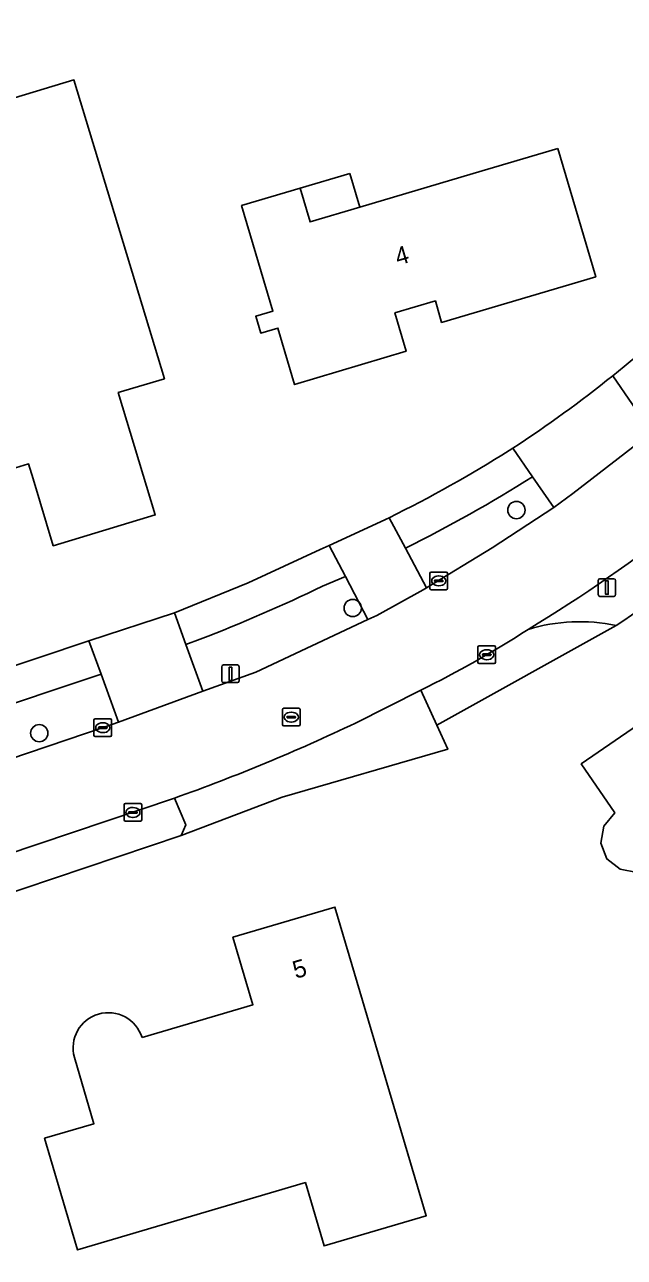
# Model space of a CAD drawing. Extents: x 162417 to 163722, y 384268 to 385417.
# Drawn here: x 163386 to 163420, y 384586 to 384656 of the extents above; entities that cross this region are included whole.
import ezdxf

# ---------------------------------------------------------------- set-up
doc = ezdxf.new("R2010")
doc.units = 0
for name, color, linetype in [('IMGEO_Berm_groen', 7, 'Continuous'), ('IMGEO_Boom', 7, 'Continuous'), ('IMGEO_Erf', 7, 'Continuous'), ('IMGEO_Groenvoorziening', 7, 'Continuous'), ('IMGEO_Kolk', 7, 'Continuous'), ('IMGEO_Lichtmast', 7, 'Continuous'), ('IMGEO_Pand', 7, 'Continuous'), ('IMGEO_Pand_nummerreeks', 7, 'Continuous'), ('IMGEO_Pand_overbouw', 7, 'Continuous'), ('IMGEO_Rijbaan_lokaal_open', 7, 'Continuous'), ('IMGEO_Rioolput', 7, 'Continuous'), ('IMGEO_Voetpad_open', 7, 'Continuous')]:
    doc.layers.add(name, color=color, linetype=linetype)

msp = doc.modelspace()

# ---------------------------------------------------------------- linework, layer by layer
at = {"layer": 'IMGEO_Berm_groen'}
for points in [[(163416.038, 384628.57), (163414.832, 384630.315)], [(163407.636, 384626.267), (163408.832, 384624.02), (163412.543, 384626.296), (163416.038, 384628.57)], [(163405.506, 384622.218), (163404.226, 384624.67), (163402.927, 384624.111)], [(163395.999, 384621.107), (163395.186, 384620.803), (163396.153, 384618.151), (163399.158, 384619.244), (163405.506, 384622.218)]]:
    msp.add_lwpolyline(points, dxfattribs=at)
msp.add_lwpolyline([(163390.546, 384616.112), (163391.36, 384616.408), (163390.37, 384619.126), (163375.772, 384614.24), (163376.658, 384611.416)], close=True, dxfattribs=at)
for centre, radius, start, end in [((163371.727, 384698.521), 80.685, 296.42647, 302.29206), ((163364.309, 384703.683), 88.448, 290.99513, 295.88824)]:
    msp.add_arc(centre, radius, start, end, dxfattribs=at)
at = {"layer": 'IMGEO_Boom'}
for centre in [(163413.924, 384628.428), (163404.643, 384622.873), (163386.868, 384615.776)]:
    msp.add_circle(centre, 0.489, dxfattribs=at)
at = {"layer": 'IMGEO_Erf'}
for points in [[(163310.09, 384681.76), (163333.508, 384602.071), (163340.928, 384604.472), (163346.471, 384606.34), (163371.048, 384614.758), (163375.186, 384616.159), (163389.679, 384621.017), (163394.532, 384622.596), (163398.708, 384624.299), (163402.801, 384626.194), (163403.314, 384626.415), (163406.716, 384627.995)], [(163413.514, 384631.806), (163413.713, 384631.935)], [(163419.582, 384621.874), (163409.408, 384616.22), (163410.03, 384614.861), (163400.639, 384612.147), (163394.917, 384609.966), (163384.126, 384606.347), (163382.571, 384605.826), (163379.98, 384604.957), (163377.103, 384603.845), (163372.405, 384602.287), (163358.873, 384597.777), (163355.069, 384596.509), (163354.943, 384596.875), (163344.075, 384593.215), (163344.183, 384592.925), (163342.307, 384592.282)], [(163403.635, 384605.913), (163405.052, 384601.119), (163408.811, 384588.401), (163403.019, 384586.69), (163401.957, 384590.287), (163389.04, 384586.469), (163388.587, 384588.004), (163387.17, 384592.799), (163389.971, 384593.627), (163388.86, 384597.387)], [(163392.697, 384598.51), (163398.987, 384600.369), (163397.853, 384604.204), (163403.635, 384605.913)]]:
    msp.add_lwpolyline(points, dxfattribs=at)
for points in [[(163392.516, 384640.667), (163393.965, 384635.882), (163391.345, 384635.089), (163393.445, 384628.155), (163387.663, 384626.41), (163386.518, 384630.192), (163386.261, 384631.043), (163384.28, 384630.444), (163384.538, 384629.593), (163380.261, 384628.298), (163379.31, 384631.443), (163376.692, 384630.651), (163375.243, 384635.437), (163374.953, 384636.394), (163377.573, 384637.187), (163376.623, 384640.332), (163382.891, 384642.229), (163381.746, 384646.012), (163380.405, 384650.271), (163388.837, 384652.823)], [(163416.266, 384648.938), (163418.425, 384641.662), (163409.685, 384639.076), (163409.329, 384640.29), (163407.033, 384639.616), (163407.664, 384637.439), (163401.35, 384635.549), (163400.4, 384638.751), (163399.431, 384638.464), (163399.146, 384639.421), (163400.114, 384639.709), (163398.338, 384645.7), (163401.655, 384646.683), (163402.221, 384644.775), (163405.042, 384645.611), (163411.472, 384647.517)], [(163423.426, 384619.015), (163423.504, 384619.857), (163425.24, 384621.047), (163426.06, 384620.847), (163426.722, 384620.31), (163434.524, 384625.652), (163437.361, 384621.535), (163444.73, 384610.844), (163436.077, 384604.88), (163431.875, 384610.985), (163423.588, 384605.386), (163421.696, 384608.187), (163420.775, 384607.881), (163419.813, 384608.066), (163419.044, 384608.641), (163418.702, 384609.538), (163418.883, 384610.501), (163419.499, 384611.264), (163417.6, 384614.035), (163423.689, 384618.208)]]:
    msp.add_lwpolyline(points, close=True, dxfattribs=at)
for centre, radius, start, end in [((163373.98, 384692.802), 72.684, 308.65684, 314.01186), ((163373.676, 384693.163), 73.156, 303.18096, 308.66682), ((163368.694, 384696.602), 90.409, 304.2543, 314.94032), ((163372.795, 384696.472), 76.418, 296.35239, 302.19812), ((163390.786, 384597.921), 1.999, 17.12637, 195.50067)]:
    msp.add_arc(centre, radius, start, end, dxfattribs=at)
at = {"layer": 'IMGEO_Groenvoorziening'}
for points in [[(163408.495, 384618.212), (163409.408, 384616.22), (163419.582, 384621.874)], [(163384.126, 384606.347), (163394.917, 384609.966), (163395.176, 384610.568), (163394.546, 384612.095), (163382.96, 384608.203)]]:
    msp.add_lwpolyline(points, dxfattribs=at)
for centre, radius, start, end in [((163417.49, 384612.22), 9.878, 77.77644, 107.10513), ((163381.624, 384672.76), 60.808, 296.2254, 302.82367)]:
    msp.add_arc(centre, radius, start, end, dxfattribs=at)
at = {"layer": 'IMGEO_Kolk'}
for p, q in [((163409.019, 384623.988), (163409.019, 384624.84)), ((163409.094, 384624.914), (163409.946, 384624.914)), ((163410.02, 384624.84), (163410.02, 384623.988)), ((163409.278, 384624.408), (163409.278, 384624.42)), ((163409.716, 384624.371), (163409.318, 384624.371)), ((163409.321, 384624.457), (163409.719, 384624.457)), ((163409.53, 384624.134), (163409.505, 384624.134)), ((163409.507, 384624.694), (163409.532, 384624.694)), ((163409.762, 384624.42), (163409.762, 384624.408)), ((163409.946, 384623.914), (163409.094, 384623.914)), ((163411.74, 384619.798), (163411.74, 384620.65)), ((163411.815, 384620.724), (163412.667, 384620.724)), ((163412.741, 384620.65), (163412.741, 384619.798)), ((163411.999, 384620.218), (163411.999, 384620.23)), ((163412.437, 384620.181), (163412.039, 384620.181)), ((163412.042, 384620.267), (163412.44, 384620.267)), ((163412.251, 384619.944), (163412.226, 384619.944)), ((163412.228, 384620.504), (163412.253, 384620.504)), ((163412.483, 384620.23), (163412.483, 384620.218)), ((163412.667, 384619.724), (163411.815, 384619.724)), ((163389.968, 384615.659), (163389.968, 384616.511)), ((163390.043, 384616.585), (163390.895, 384616.585)), ((163390.456, 384616.365), (163390.481, 384616.365)), ((163390.969, 384616.511), (163390.969, 384615.659)), ((163390.227, 384616.079), (163390.227, 384616.091)), ((163390.665, 384616.042), (163390.267, 384616.042)), ((163390.27, 384616.128), (163390.668, 384616.128)), ((163390.479, 384615.805), (163390.454, 384615.805)), ((163390.711, 384616.091), (163390.711, 384616.079)), ((163390.895, 384615.585), (163390.043, 384615.585)), ((163391.677, 384610.854), (163391.677, 384611.706)), ((163391.752, 384611.78), (163392.604, 384611.78)), ((163392.165, 384611.56), (163392.19, 384611.56)), ((163392.678, 384611.706), (163392.678, 384610.854)), ((163392.604, 384610.78), (163391.752, 384610.78)), ((163391.936, 384611.274), (163391.936, 384611.286)), ((163392.374, 384611.237), (163391.976, 384611.237)), ((163391.979, 384611.323), (163392.377, 384611.323)), ((163392.188, 384611), (163392.163, 384611)), ((163392.42, 384611.286), (163392.42, 384611.274))]:
    msp.add_line(p, q, dxfattribs=at)
for points in [[(163409.019, 384623.988), (163409.019, 384624.84)], [(163409.094, 384624.914), (163409.946, 384624.914)], [(163410.02, 384624.84), (163410.02, 384623.988)], [(163409.946, 384623.914), (163409.094, 384623.914)], [(163411.74, 384619.798), (163411.74, 384620.65)], [(163411.815, 384620.724), (163412.667, 384620.724)], [(163412.741, 384620.65), (163412.741, 384619.798)], [(163412.667, 384619.724), (163411.815, 384619.724)], [(163389.968, 384615.659), (163389.968, 384616.511)], [(163390.043, 384616.585), (163390.895, 384616.585)], [(163390.969, 384616.511), (163390.969, 384615.659)], [(163390.895, 384615.585), (163390.043, 384615.585)], [(163391.677, 384610.854), (163391.677, 384611.706)], [(163391.752, 384611.78), (163392.604, 384611.78)], [(163392.678, 384611.706), (163392.678, 384610.854)], [(163392.604, 384610.78), (163391.752, 384610.78)]]:
    msp.add_lwpolyline(points, dxfattribs=at)
for centre, radius, start, end in [((163409.096, 384624.838), 0.0765, 91.55205, 178.44795), ((163409.096, 384624.838), 0.0765, 91.55205, 178.44795), ((163409.944, 384624.838), 0.0765, 1.55205, 88.44795), ((163409.944, 384624.838), 0.0765, 1.55205, 88.44795), ((163409.318, 384624.417), 0.0403, 85.87752, 175.75265), ((163409.315, 384624.407), 0.0366, 178.93798, 274.71019), ((163409.719, 384624.414), 0.043, 264.86636, 352.45326), ((163409.723, 384624.419), 0.0386, 1.73085, 96.63898), ((163409.096, 384623.99), 0.0765, 181.55205, 268.44795), ((163409.096, 384623.99), 0.0765, 181.55205, 268.44795), ((163409.944, 384623.99), 0.0765, 271.55205, 358.44795), ((163409.944, 384623.99), 0.0765, 271.55205, 358.44795), ((163411.817, 384620.648), 0.0765, 91.55205, 178.44795), ((163411.817, 384620.648), 0.0765, 91.55205, 178.44795), ((163412.665, 384620.648), 0.0765, 1.55205, 88.44795), ((163412.665, 384620.648), 0.0765, 1.55205, 88.44795), ((163412.039, 384620.227), 0.0403, 85.87752, 175.75265), ((163412.036, 384620.217), 0.0366, 178.93798, 274.71019), ((163412.44, 384620.224), 0.043, 264.86636, 352.45326), ((163412.444, 384620.229), 0.0386, 1.73085, 96.63898), ((163411.817, 384619.8), 0.0765, 181.55205, 268.44795), ((163411.817, 384619.8), 0.0765, 181.55205, 268.44795), ((163412.665, 384619.8), 0.0765, 271.55205, 358.44795), ((163412.665, 384619.8), 0.0765, 271.55205, 358.44795), ((163390.045, 384616.509), 0.0765, 91.55205, 178.44795), ((163390.045, 384616.509), 0.0765, 91.55205, 178.44795), ((163390.893, 384616.509), 0.0765, 1.55205, 88.44795), ((163390.893, 384616.509), 0.0765, 1.55205, 88.44795), ((163390.045, 384615.661), 0.0765, 181.55205, 268.44795), ((163390.045, 384615.661), 0.0765, 181.55205, 268.44795), ((163390.267, 384616.088), 0.0403, 85.87752, 175.75265), ((163390.264, 384616.078), 0.0366, 178.93798, 274.71019), ((163390.668, 384616.085), 0.043, 264.86636, 352.45326), ((163390.672, 384616.09), 0.0386, 1.73085, 96.63898), ((163390.893, 384615.661), 0.0765, 271.55205, 358.44795), ((163390.893, 384615.661), 0.0765, 271.55205, 358.44795), ((163391.754, 384611.704), 0.0765, 91.55205, 178.44795), ((163391.754, 384611.704), 0.0765, 91.55205, 178.44795), ((163392.602, 384611.704), 0.0765, 1.55205, 88.44795), ((163392.602, 384611.704), 0.0765, 1.55205, 88.44795), ((163391.754, 384610.856), 0.0765, 181.55205, 268.44795), ((163391.754, 384610.856), 0.0765, 181.55205, 268.44795), ((163391.976, 384611.283), 0.0403, 85.87752, 175.75265), ((163391.973, 384611.273), 0.0366, 178.93798, 274.71019), ((163392.377, 384611.28), 0.043, 264.86636, 352.45326), ((163392.381, 384611.285), 0.0386, 1.73085, 96.63898), ((163392.602, 384610.856), 0.0765, 271.55205, 358.44795), ((163392.602, 384610.856), 0.0765, 271.55205, 358.44795)]:
    msp.add_arc(centre, radius, start, end, dxfattribs=at)
for centre, major_axis, ratio, start_param, end_param in [((163409.506, 384624.414), (-0.387, 0.002), 0.722429, 4.712389, 7.853982), ((163409.531, 384624.414), (-0.39, 0.002), 0.717154, 1.570796, 4.712389), ((163412.227, 384620.224), (-0.387, 0.002), 0.722429, 4.712389, 7.853982), ((163412.252, 384620.224), (-0.39, 0.002), 0.717154, 1.570796, 4.712389), ((163390.455, 384616.085), (-0.387, 0.002), 0.722429, 4.712389, 7.853982), ((163390.48, 384616.085), (-0.39, 0.002), 0.717154, 1.570796, 4.712389), ((163392.164, 384611.28), (-0.387, 0.002), 0.722429, 4.712389, 7.853982), ((163392.189, 384611.28), (-0.39, 0.002), 0.717154, 1.570796, 4.712389)]:
    msp.add_ellipse(centre, major_axis=major_axis, ratio=ratio, start_param=start_param, end_param=end_param, dxfattribs=at)
at = {"layer": 'IMGEO_Lichtmast'}
for p, q in [((163418.56, 384623.632), (163418.56, 384624.432)), ((163418.56, 384624.432), (163418.56, 384623.632)), ((163418.66, 384624.532), (163419.45, 384624.532)), ((163419.45, 384624.532), (163418.66, 384624.532)), ((163419.55, 384624.432), (163419.55, 384623.632)), ((163419.55, 384623.632), (163419.55, 384624.432)), ((163419.45, 384623.532), (163418.66, 384623.532)), ((163418.66, 384623.532), (163419.45, 384623.532)), ((163397.213, 384618.742), (163397.213, 384619.542)), ((163397.213, 384619.542), (163397.213, 384618.742)), ((163397.313, 384619.642), (163398.103, 384619.642)), ((163398.103, 384619.642), (163397.313, 384619.642)), ((163398.203, 384619.542), (163398.203, 384618.742)), ((163398.203, 384618.742), (163398.203, 384619.542)), ((163398.103, 384618.642), (163397.313, 384618.642)), ((163397.313, 384618.642), (163398.103, 384618.642))]:
    msp.add_line(p, q, dxfattribs=at)
for points in [[(163418.98, 384624.407), (163419.13, 384624.407), (163419.13, 384623.657), (163418.98, 384623.657), (163418.98, 384624.407)], [(163397.633, 384619.517), (163397.783, 384619.517), (163397.783, 384618.767), (163397.633, 384618.767), (163397.633, 384619.517)]]:
    msp.add_lwpolyline(points, dxfattribs=at)
for centre, start, end in [((163418.66, 384624.432), 90, 180), ((163418.66, 384624.432), 90, 180), ((163419.45, 384624.432), 0, 90), ((163419.45, 384624.432), 360, 90), ((163418.66, 384623.632), 180, 270), ((163418.66, 384623.632), 180, 270), ((163419.45, 384623.632), 270, 0), ((163419.45, 384623.632), 270, 0), ((163397.313, 384619.542), 90, 180), ((163397.313, 384619.542), 90, 180), ((163398.103, 384619.542), 0, 90), ((163398.103, 384619.542), 360, 90), ((163397.313, 384618.742), 180, 270), ((163397.313, 384618.742), 180, 270), ((163398.103, 384618.742), 270, 0), ((163398.103, 384618.742), 270, 0)]:
    msp.add_arc(centre, 0.1, start, end, dxfattribs=at)
at = {"layer": 'IMGEO_Pand'}
for points in [[(163375.243, 384635.437), (163376.692, 384630.651), (163379.31, 384631.443), (163380.261, 384628.298), (163384.538, 384629.593), (163384.28, 384630.444), (163386.261, 384631.043), (163386.518, 384630.192), (163387.663, 384626.41), (163393.445, 384628.155), (163391.345, 384635.089), (163393.965, 384635.882), (163392.516, 384640.667), (163388.837, 384652.823), (163380.405, 384650.271), (163381.746, 384646.012), (163382.891, 384642.229), (163376.623, 384640.332), (163377.573, 384637.187), (163374.953, 384636.394)], [(163416.266, 384648.938), (163411.472, 384647.517), (163405.042, 384645.611), (163402.221, 384644.775), (163401.655, 384646.683), (163398.338, 384645.7), (163400.114, 384639.709), (163399.146, 384639.421), (163399.431, 384638.464), (163400.4, 384638.751), (163401.35, 384635.549), (163407.664, 384637.439), (163407.033, 384639.616), (163409.329, 384640.29), (163409.685, 384639.076), (163418.425, 384641.662)], [(163419.499, 384611.264), (163418.883, 384610.501), (163418.702, 384609.538), (163419.044, 384608.641), (163419.813, 384608.066), (163420.775, 384607.881), (163421.696, 384608.187), (163423.588, 384605.386), (163431.875, 384610.985), (163436.077, 384604.88), (163444.73, 384610.844), (163437.361, 384621.535), (163434.524, 384625.652), (163426.722, 384620.31), (163426.06, 384620.847), (163425.24, 384621.047), (163423.504, 384619.857), (163423.426, 384619.015), (163423.689, 384618.208), (163417.6, 384614.035)]]:
    msp.add_lwpolyline(points, close=True, dxfattribs=at)
msp.add_lwpolyline([(163388.86, 384597.387), (163389.971, 384593.627), (163387.17, 384592.799), (163388.587, 384588.004), (163389.04, 384586.469), (163401.957, 384590.287), (163403.019, 384586.69), (163408.811, 384588.401), (163405.052, 384601.119), (163403.635, 384605.913), (163397.853, 384604.204), (163398.987, 384600.369), (163392.697, 384598.51)], dxfattribs=at)
msp.add_arc((163390.786, 384597.921), 1.999, 17.12637, 195.50067, dxfattribs=at)
at = {"layer": 'IMGEO_Pand_overbouw'}
msp.add_lwpolyline([(163404.476, 384647.519), (163401.655, 384646.683), (163402.221, 384644.775), (163405.042, 384645.611)], close=True, dxfattribs=at)
at = {"layer": 'IMGEO_Rijbaan_lokaal_open'}
for points in [[(163421.605, 384632.827), (163417.131, 384629.372), (163416.038, 384628.57), (163412.543, 384626.296), (163408.832, 384624.02), (163408.641, 384623.903), (163406.014, 384622.456), (163405.506, 384622.218), (163399.158, 384619.244), (163396.153, 384618.151), (163391.36, 384616.408), (163390.546, 384616.112), (163376.658, 384611.416)], [(163404.799, 384616.348), (163408.495, 384618.212)], [(163317.177, 384586.045), (163324.882, 384588.717), (163325.068, 384588.78), (163335.735, 384592.381), (163354.346, 384598.613), (163358.243, 384599.918), (163371.696, 384604.423), (163376.389, 384605.995), (163381.515, 384607.717), (163382.96, 384608.203), (163394.546, 384612.095)]]:
    msp.add_lwpolyline(points, dxfattribs=at)
for centre, radius, start, end in [((163370.506, 384694.597), 85.221, 301.14686, 315.76166), ((163381.624, 384672.76), 60.808, 296.2254, 302.82367), ((163357.584, 384715.688), 109.99, 289.63659, 295.42129)]:
    msp.add_arc(centre, radius, start, end, dxfattribs=at)
at = {"layer": 'IMGEO_Rioolput'}
for p, q in [((163400.657, 384616.26), (163400.657, 384617.112)), ((163400.732, 384617.186), (163401.584, 384617.186)), ((163401.658, 384617.112), (163401.658, 384616.26)), ((163400.916, 384616.68), (163400.916, 384616.692)), ((163401.354, 384616.643), (163400.956, 384616.643)), ((163400.959, 384616.729), (163401.357, 384616.729)), ((163401.168, 384616.406), (163401.143, 384616.406)), ((163401.145, 384616.966), (163401.17, 384616.966)), ((163401.4, 384616.692), (163401.4, 384616.68)), ((163401.584, 384616.186), (163400.732, 384616.186))]:
    msp.add_line(p, q, dxfattribs=at)
for points in [[(163400.657, 384616.26), (163400.657, 384617.112)], [(163400.732, 384617.186), (163401.584, 384617.186)], [(163401.658, 384617.112), (163401.658, 384616.26)], [(163401.584, 384616.186), (163400.732, 384616.186)]]:
    msp.add_lwpolyline(points, dxfattribs=at)
for centre, radius, start, end in [((163400.734, 384617.11), 0.0765, 91.55205, 178.44795), ((163400.734, 384617.11), 0.0765, 91.55205, 178.44795), ((163401.582, 384617.11), 0.0765, 1.55205, 88.44795), ((163401.582, 384617.11), 0.0765, 1.55205, 88.44795), ((163400.956, 384616.689), 0.0403, 85.87752, 175.75265), ((163400.953, 384616.679), 0.0366, 178.93798, 274.71019), ((163401.357, 384616.686), 0.043, 264.86636, 352.45326), ((163401.361, 384616.691), 0.0386, 1.73085, 96.63898), ((163400.734, 384616.262), 0.0765, 181.55205, 268.44795), ((163400.734, 384616.262), 0.0765, 181.55205, 268.44795), ((163401.582, 384616.262), 0.0765, 271.55205, 358.44795), ((163401.582, 384616.262), 0.0765, 271.55205, 358.44795)]:
    msp.add_arc(centre, radius, start, end, dxfattribs=at)
for centre, major_axis, ratio, start_param, end_param in [((163401.144, 384616.686), (-0.387, 0.002), 0.722429, 4.712389, 7.853982), ((163401.169, 384616.686), (-0.39, 0.002), 0.717154, 1.570796, 4.712389)]:
    msp.add_ellipse(centre, major_axis=major_axis, ratio=ratio, start_param=start_param, end_param=end_param, dxfattribs=at)
at = {"layer": 'IMGEO_Voetpad_open'}
for points in [[(163413.713, 384631.935), (163414.832, 384630.315), (163416.038, 384628.57), (163417.131, 384629.372), (163421.605, 384632.827), (163420.504, 384634.421), (163419.383, 384636.043)], [(163419.383, 384636.043), (163420.504, 384634.421)], [(163414.832, 384630.315), (163413.713, 384631.935), (163413.514, 384631.806)], [(163406.716, 384627.995), (163407.636, 384626.267)], [(163402.927, 384624.111), (163404.226, 384624.67), (163403.314, 384626.415), (163402.801, 384626.194), (163398.708, 384624.299), (163394.532, 384622.596), (163395.186, 384620.803), (163395.999, 384621.107)], [(163394.546, 384612.095), (163395.176, 384610.568), (163394.917, 384609.966), (163400.639, 384612.147), (163410.03, 384614.861), (163409.408, 384616.22), (163408.495, 384618.212), (163404.799, 384616.348)]]:
    msp.add_lwpolyline(points, dxfattribs=at)
for points in [[(163406.716, 384627.995), (163403.314, 384626.415), (163404.226, 384624.67), (163405.506, 384622.218), (163406.014, 384622.456), (163408.641, 384623.903), (163408.832, 384624.02), (163407.636, 384626.267)], [(163391.36, 384616.408), (163396.153, 384618.151), (163395.186, 384620.803), (163394.532, 384622.596), (163389.679, 384621.017), (163390.37, 384619.126)], [(163375.772, 384614.24), (163390.37, 384619.126), (163389.679, 384621.017), (163375.186, 384616.159)]]:
    msp.add_lwpolyline(points, close=True, dxfattribs=at)
for centre, radius, start, end in [((163373.98, 384692.802), 72.684, 308.65684, 314.01186), ((163373.676, 384693.163), 73.156, 303.18096, 308.66682), ((163370.506, 384694.597), 85.221, 301.14686, 315.76166), ((163368.694, 384696.602), 90.409, 304.2543, 314.94032), ((163372.795, 384696.472), 76.418, 296.35239, 302.19812), ((163371.727, 384698.521), 80.685, 296.42647, 302.29206), ((163364.309, 384703.683), 88.448, 290.99513, 295.88824), ((163417.49, 384612.22), 9.878, 77.77644, 107.10513), ((163357.584, 384715.688), 109.99, 289.63659, 295.42129)]:
    msp.add_arc(centre, radius, start, end, dxfattribs=at)

# ---------------------------------------------------------------- texts
at = {"layer": 'IMGEO_Pand_nummerreeks'}
for s, rotation, p in [('4', 16.35795, (163407.207, 384642.293)), ('5', 16.46623, (163401.41, 384601.834))]:
    msp.add_text(s, height=1, rotation=rotation, dxfattribs=at).set_placement(p)

doc.saveas('drawing.dxf')
